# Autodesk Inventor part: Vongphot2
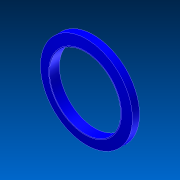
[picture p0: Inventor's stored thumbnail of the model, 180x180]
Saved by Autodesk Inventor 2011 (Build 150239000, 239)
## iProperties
Created: 2011-05
Part Number: Vongphot2
Document SubType Name: Modeling
Designer: 904Chiaki
Density: 1 g/cm^3
Author: 904Chiaki
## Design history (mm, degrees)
sketch "Sketch1"
  geometry: L1 (-37.164, 16.359)-(-37.164, -9.86); L2 (4.836, -4.178)-(4.836, -0.928); L3 (4.836, -0.928)-(-3.914, 0.322); L4 (4.836, -7.428)-(-3.914, -8.678); L5 (4.836, -4.178)-(4.836, -7.428); L6 (-4.664, 0.322)-(-4.664, -8.678); L7 (-3.914, 0.322)-(-4.664, 0.322); L8 (-3.914, -8.678)-(-4.664, -8.678); 1 further point
  constraints: 16 end point
  dimensions: "d0" = 9 distance of L3.end L4.end; "d3" = 3.25 distance of L2.start L2.end; "d4" = 32.5 distance between parallel lines of L1 L6
revolve "Revolution1" sketch "Sketch1" stored, may be unused: angle "d5" = 90 deg
body "Solid1"
